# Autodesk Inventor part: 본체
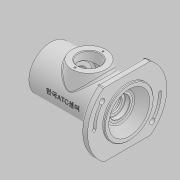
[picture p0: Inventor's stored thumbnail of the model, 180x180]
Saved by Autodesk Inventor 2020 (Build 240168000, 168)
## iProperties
Created: 2022-05
Part Number: 본체
Material: 일반
Document SubType Name: Modeling
Designer: User
Density: 1 g/cm^3
Appearance: 기본값
Author: User
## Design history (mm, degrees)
sketch "스케치1"
  geometry: L1 (-57.5, 0)-(-57.5, 32); L2 (-57.5, 32)-(44.5, 32); L3 (44.5, 32)-(44.5, 58); L4 (44.5, 58)-(54.5, 58); L5 (54.5, 58)-(54.5, 36); L6 (54.5, 36)-(57.5, 36); L7 (57.5, 36)-(57.5, 0); L8 (57.5, 0)-(-57.5, 0); L9 (-49.5, 0)-(-49.5, 24); L10 (-49.5, 24)-(-46.5, 24); L11 (-46.5, 24)-(-46.5, 22.5); L12 (-46.5, 22.5)-(-35.5, 22.5); L13 (-35.5, 22.5)-(-35.5, 17.5); L14 (-35.5, 17.5)-(-33.25, 17.5); L15 (-33.25, 17.5)-(-33.25, 18.5); L16 (-33.25, 18.5)-(-31.5, 18.5); L17 (-31.5, 18.5)-(-31.5, 17.5); L18 (-31.5, 17.5)-(-20.5, 17.5); L19 (-20.5, 17.5)-(-20.5, 27); L20 (-20.5, 27)-(17.5, 27); L21 (17.5, 27)-(17.5, 17.5); L22 (17.5, 17.5)-(28.5, 17.5); L23 (28.5, 17.5)-(28.5, 15); L24 (28.5, 15)-(33.5, 15); L25 (33.5, 15)-(33.5, 11); L26 (33.5, 11)-(36.2, 11); L27 (36.2, 11)-(36.2, 15); L28 (36.2, 15)-(43.5, 15); L29 (43.5, 15)-(43.5, 20); L30 (43.5, 20)-(57.5, 30); 2 further points
  constraints: 60 end point, 24 perpendicular, 6 point on line, 1 coincident, 1 horizontal, 1 midpoint, 1 parallel, 1 vertical
  dimensions: "d0" = 115 distance of L7.end L1.start; "d1" = 3 distance of L5.end L6.end; "d2" = 10 distance of L3.end L4.end; "d3" = 64 diameter of L2 L8; "d4" = 72 diameter of L6 L8; "d5" = 116 diameter of L4 L8; "d6" = 48 diameter of L10 L8; "d7" = 45 diameter of L12 L8; "d8" = 35 diameter of L14 L8; "d9" = 37 diameter of L16 L8; "d10" = 54 diameter of L20 L8; "d12" = 30 diameter of L24 L8; "d13" = 22 diameter of L26 L8; "d14" = 30 diameter of L28 L8; "d15" = 40 diameter of L29.end L8; "d16" = 60 diameter of L30.end L8; "d17" = 14 distance between parallel lines of L7 L29; "d18" = 29 distance between parallel lines of L7 L23; "d19" = 5 distance of L23.end L24.end; "d20" = 7.3 distance of L27.end L28.end; "d21" = 11 distance between parallel lines of L21 L23; "d22" = 11 distance between parallel lines of L19 L17; "d23" = 38 distance of L19.end L20.end; "d24" = 3 distance of L9.end L10.end; "d25" = 22 distance between parallel lines of L1 L13; "d26" = 8 distance between parallel lines of L1 L9; "d27" = 1.75 distance of L15.end L16.end
revolve "회전1" sketch "스케치1" stored, may be unused: angle "d28" = 90 deg
sketch "스케치2"
  geometry: L1 (-33.985, 47)-(33.985, 47); L2 (-33.985, -47)-(33.985, -47); A1 r 58 centre (0, 0) between (-33.985, 47) and (33.985, 47) reference; 1 further point
  constraints: 4 end point, 4 point on circle, 1 horizontal, 1 parallel
  dimensions: "d29" = 94 distance between parallel lines of L2 L1; "d30" = 47 distance from line of point (0, 0) L1
extrude "돌출1" cut sketch "스케치2" extent not by distance; stored distance "d31" = 0; taper "d32" = 0 deg
sketch "스케치3"
  geometry: L1 (0, 0)-(36.77, 30.854); L2 (0, 0)-(-36.77, -30.854); L3 (-48, 0)-(48, 0); A1 r 48 centre (0, 0) between (48, 0) and (36.77, 30.854); A2 r 52 centre (0, 0) between (52, 0) and (39.834, 33.425); A3 r 44 centre (0, 0) between (44, 0) and (33.706, 28.283); A4 r 4 centre (48, 0) between (44, 0) and (52, 0); A5 r 4 centre (36.77, 30.854) between (39.834, 33.425) and (33.706, 28.283); A6 r 48 centre (0, 0) between (-48, 0) and (-36.77, -30.854); A7 r 52 centre (0, 0) between (-52, 0) and (-39.834, -33.425); A8 r 44 centre (0, 0) between (-44, 0) and (-33.706, -28.283); A9 r 4 centre (-48, 0) between (-44, 0) and (-52, 0); A10 r 4 centre (-36.77, -30.854) between (-39.834, -33.425) and (-33.706, -28.283); A11 r 45.75 centre (0, 0) between (-45.75, 0) and (-35.047, -29.408); A12 r 2.25 centre (-48, 0) between (-45.75, 0) and (-50.25, 0); A13 r 50.25 centre (0, 0) between (-50.25, 0) and (-38.494, -32.3); A14 r 2.25 centre (-36.77, -30.854) between (-38.494, -32.3) and (-35.047, -29.408); A15 r 45.75 centre (0, 0) between (45.75, 0) and (35.047, 29.408); A16 r 2.25 centre (48, 0) between (45.75, 0) and (50.25, 0); A17 r 50.25 centre (0, 0) between (50.25, 0) and (38.494, 32.3); A18 r 2.25 centre (36.77, 30.854) between (38.494, 32.3) and (35.047, 29.408); 1 further point
  constraints: 36 point on circle, 18 centre point, 8 tangent, 6 end point, 2 coincident, 2 horizontal alignment, 1 horizontal, 6 other
  dimensions: "d33" = 48 radius of A6; "d34" = 48 radius of A1; "d35" = 4 radius of A5; "d36" = 4 radius of A9; "d37" = 40 deg angle of L3 L1; "d38" = 40 deg angle of L3 L2; "d41" = 4.5 radial gap between concentric circles of A13 A11; "d42" = 4.5 radial gap between concentric circles of A17 A15
extrude "돌출2" cut sketch "스케치3" distance "d39" = 4.4; taper "d40" = 0 deg
extrude "돌출3" cut sketch "스케치3" extent not by distance; stored distance "d43" = 102; taper "d44" = 0 deg
sketch "스케치4"
  geometry: L1 (-58, 0)-(58, 0); L2 (-52.193, -43.795)-(52.193, 43.795); A1 r 58 centre (0, 0) between (-33.985, 47) and (-33.985, -47) reference; A2 r 58 centre (0, 0) between (33.985, -47) and (33.985, 47) reference; A3 r 48 centre (0, 0) between (-36.77, -30.854) and (36.77, 30.854); 2 further points
  constraints: 4 end point, 4 point on circle, 2 midpoint, 2 point on line, 1 centre point, 1 coincident
  dimensions: "d45" = 40 deg angle of L1 L2; "d46" = 96 diameter of A3
hole "구멍1" sketch "스케치4" at (-36.77, -30.854), (36.77, 30.854) diameter "d47" = 8; stored, may be unused: countersink angle "d51" = 60 deg, drill point angle "d53" = 118 deg; dims "d48" = 6, "d49" = 4.25, "d50" = 2, "d52" = 6
sketch "스케치5"
  geometry: C1 r 32 at (0, 0) reference; 2 further points
  constraints: 1 coincident
hole "구멍2" sketch "스케치5" at (0, 0) diameter "d54" = 43.376; stored, may be unused: countersink angle "d58" = 60 deg, drill point angle "d60" = 0 deg; dims "d55" = 90, "d56" = 4.25, "d57" = 2, "d59" = 8
node "작업 평면1"
sketch "스케치6"
  geometry: L1 (57.5, 32)-(57.5, -32) reference; C1 r 25 at (1.5, 0); 1 further point
  constraints: 1 centre point, 1 horizontal alignment
  dimensions: "d62" = 50 diameter of C1; "d63" = 56 distance from line of C1.centre L1
extrude "돌출4" join sketch "스케치6" stored distance "d64" = 4.4; taper "d65" = 10 deg
sketch "스케치7"
  geometry: C1 r 25 at (0, 0) reference; 2 further points
  constraints: 1 coincident
hole "구멍3" sketch "스케치7" at (0, 0) diameter "d66" = 32; stored, may be unused: countersink angle "d70" = 60 deg, drill point angle "d72" = 0 deg; dims "d67" = 90, "d68" = 4.25, "d69" = 2, "d71" = 20
fillet "모깎기1" dims "d73" = 3
fillet "모깎기2" dims "d74" = 0.6, "d75" = 0.5
chamfer "모따기1" distance "d76" = 1; stored, may be unused: second distance "d77" = 2, angle "d78" = 45 deg
chamfer "모따기2" distance "d79" = 1; stored, may be unused: second distance "d80" = 2, angle "d81" = 45 deg
chamfer "모따기3" distance "d82" = 0.7; stored, may be unused: second distance "d83" = 2, angle "d84" = 30 deg
sketch "스케치8" dims "d85" = 41
  geometry: L1 (0, 0)-(0, 20.5); C1 r 16 at (0, 0) reference; 2 further points
  constraints: 2 coincident, 2 end point, 1 vertical, 1 vertical alignment, 2 other
hole "구멍4" sketch "스케치8" at (0, 20.5) diameter "d86" = 2.62111; stored, may be unused: countersink angle "d90" = 60 deg, drill point angle "d92" = 118 deg; dims "d87" = 6, "d88" = 4.25, "d89" = 2, "d91" = 8
chamfer "모따기4" distance "d96" = 1; stored, may be unused: second distance "d97" = 2, angle "d98" = 30 deg
node "작업 평면2"
sketch "스케치9"
  geometry: L1 (61, -47)-(61, 47) reference; 2 further points
  constraints: 1 horizontal alignment, 1 other
  dimensions: "d99" = 62 distance from line of L1 point (-1, 0)
feature "엠보싱1" sketch "스케치9" dims "d0" = 115, "d1" = 3, "d2" = 10, "d3" = 64, "d4" = 72, "d5" = 116, "d6" = 48, "d7" = 45, "d8" = 35, "d9" = 37, "d10" = 54, "d12" = 30, "d13" = 22, "d14" = 30, "d15" = 40, "d16" = 60, "d17" = 14, "d18" = 29, "d19" = 5, "d20" = 7.3, "d21" = 11, "d22" = 11, "d23" = 38, "d24" = 3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
chamfer "모따기5" distance "d102" = 1; stored, may be unused: second distance "d103" = 2, angle "d104" = 30 deg
fillet "모깎기3" dims "d105" = 3
fillet "모깎기4" dims "d106" = 3
node "솔리드1"
pattern_circular "원형 패턴1" dims angle "d94" = 360 deg
feature "A9D066F2-1C7D-4E18-AEED-F7BC21143FA4" dims "d47" = 8, "d48" = 6, "d49" = 4.25, "d50" = 2, "d51" = 60 deg, "d52" = 6, "d53" = 118 deg
other parameters: "d61" = 38
